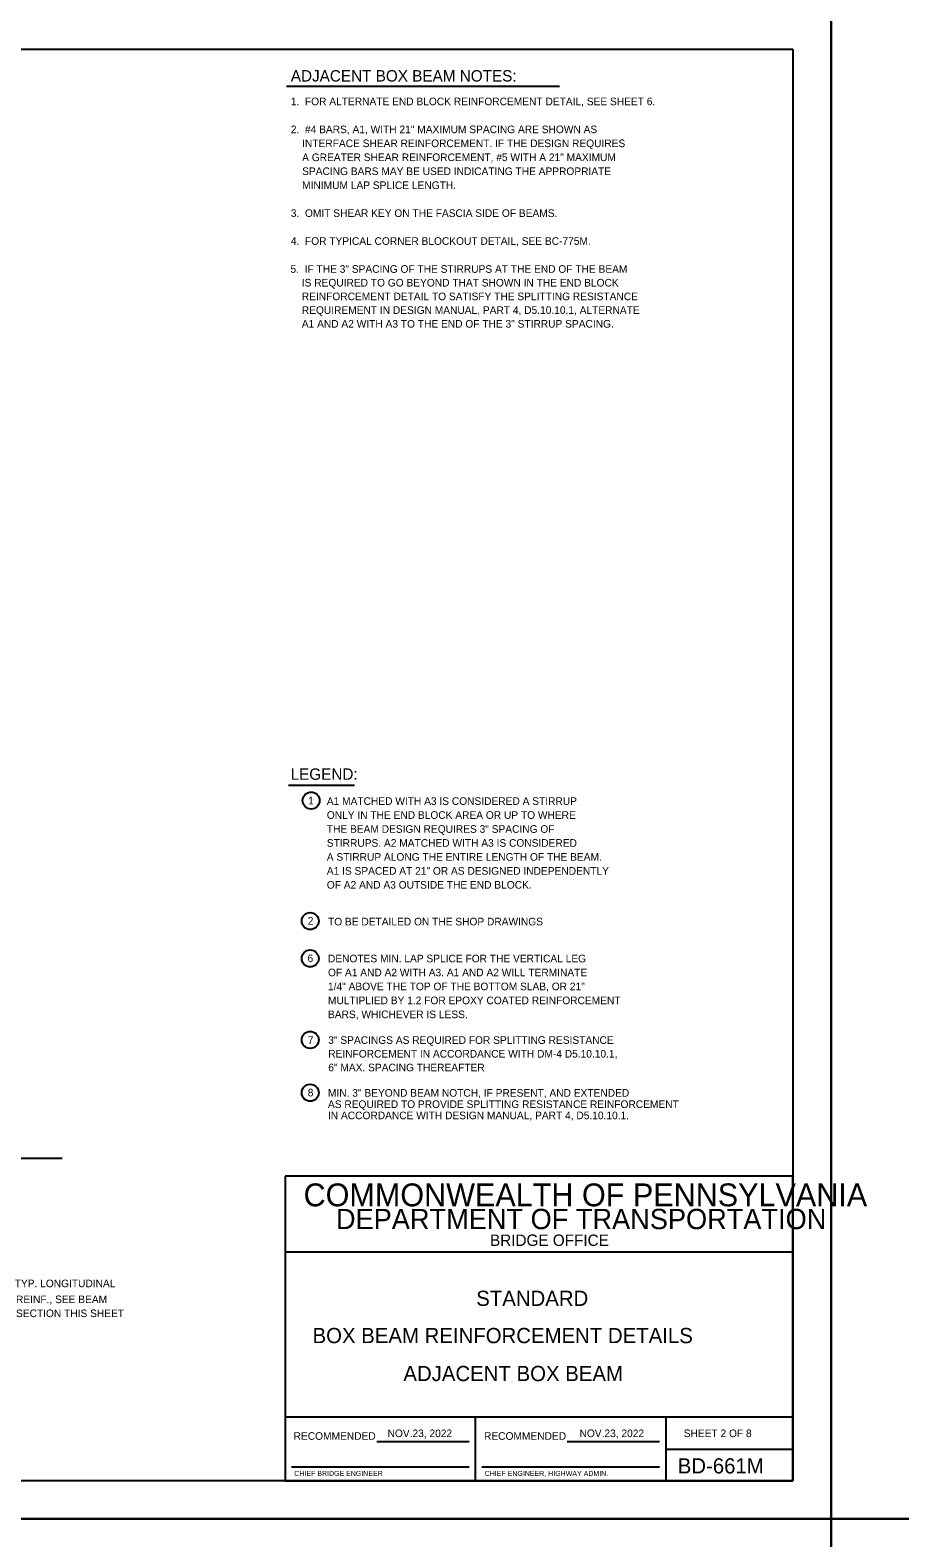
# Model space of a CAD drawing. Extents: x 639331 to 643089, y 299088 to 300975.
# Drawn here: x 641078 to 641420, y 299674 to 300268 of the extents above; entities that cross this region are included whole.
import ezdxf

# ---------------------------------------------------------------- set-up
doc = ezdxf.new("R2010")
doc.units = 0
for name, color, linetype in [('1', 7, 'Continuous'), ('DATES', 7, 'Continuous'), ('PLT-BNDY', 7, 'Continuous'), ('SIGNATORY TITLES', 7, 'Continuous')]:
    doc.layers.add(name, color=color, linetype=linetype)

msp = doc.modelspace()

# ---------------------------------------------------------------- linework, layer by layer
at = {"layer": '1'}
for p, q in [((640592.06, 300260.66), (641378.06, 300260.66)), ((641378.06, 300260.66), (641378.06, 299696.66)), ((641286.13, 300245.94), (641178.53, 300245.94)), ((641179.37, 299970.66), (641205.43, 299970.66)), ((641090.27, 299823.64), (640920.4, 299823.64)), ((641378.06, 299816.66), (641178.06, 299816.66)), ((641178.06, 299816.66), (641178.06, 299696.66)), ((641378.06, 299696.66), (641378.06, 299816.66)), ((641378.06, 299786.66), (641178.06, 299786.66)), ((641378.06, 299721.66), (641178.06, 299721.66)), ((641253.06, 299696.66), (641253.06, 299721.66)), ((641328.06, 299721.66), (641328.06, 299696.66)), ((641214.15, 299712.16), (641250.56, 299712.16)), ((641289.15, 299712.16), (641325.56, 299712.16)), ((641328.06, 299709.16), (641378.06, 299709.16)), ((641180.56, 299702.16), (641250.56, 299702.16)), ((641255.56, 299702.16), (641325.56, 299702.16)), ((641378.06, 299696.66), (640592.06, 299696.66)), ((641178.06, 299696.66), (641378.06, 299696.66))]:
    msp.add_line(p, q, dxfattribs=at)
for centre in [(641188.28, 299964.63), (641187.92, 299917.17), (641187.92, 299902.41), (641187.92, 299870.33), (641187.92, 299849.52)]:
    msp.add_circle(centre, 3.35, dxfattribs=at)
at = {"layer": 'PLT-BNDY'}
for points in [[(640552.06, 300275.66), (641393.06, 300275.66), (641393.06, 299681.66), (640552.06, 299681.66)], [(641393.06, 300275.66), (642234.06, 300275.66), (642234.06, 299681.66), (641393.06, 299681.66)], [(640552.06, 299681.66), (641393.06, 299681.66), (641393.06, 299087.66), (640552.06, 299087.66)], [(641393.06, 299681.66), (642234.06, 299681.66), (642234.06, 299087.66), (641393.06, 299087.66)]]:
    msp.add_lwpolyline(points, close=True, dxfattribs=at)

# ---------------------------------------------------------------- texts
at = {"layer": '1'}
for s, height, p in [('ADJACENT BOX BEAM NOTES:', 4.5, (641180.28, 300247.91)), ('1.  FOR ALTERNATE END BLOCK REINFORCEMENT DETAIL, SEE SHEET 6.', 3, (641180.28, 300238.57)), ('2.  #4 BARS, A1, WITH 21" MAXIMUM SPACING ARE SHOWN AS', 3, (641180.28, 300227.57)), ('    A GREATER SHEAR REINFORCEMENT, #5 WITH A 21" MAXIMUM', 3, (641180.28, 300216.57)), ('    INTERFACE SHEAR REINFORCEMENT. IF THE DESIGN REQUIRES', 3, (641180.28, 300222.07)), ('    SPACING BARS MAY BE USED INDICATING THE APPROPRIATE', 3, (641180.28, 300211.07)), ('    MINIMUM LAP SPLICE LENGTH.', 3, (641180.28, 300205.57)), ('3.  OMIT SHEAR KEY ON THE FASCIA SIDE OF BEAMS.', 3, (641180.28, 300194.57)), ('4.  FOR TYPICAL CORNER BLOCKOUT DETAIL, SEE BC-775M.', 3, (641180.28, 300183.57)), ('5.  IF THE 3" SPACING OF THE STIRRUPS AT THE END OF THE BEAM', 3, (641180.15, 300172.56)), ('    IS REQUIRED TO GO BEYOND THAT SHOWN IN THE END BLOCK', 3, (641180.15, 300167.16)), ('    REINFORCEMENT DETAIL TO SATISFY THE SPLITTING RESISTANCE', 3, (641180.15, 300161.76)), ('    REQUIREMENT IN DESIGN MANUAL, PART 4, D5.10.10.1, ALTERNATE', 3, (641180.15, 300156.36)), ('    A1 AND A2 WITH A3 TO THE END OF THE 3" STIRRUP SPACING.', 3, (641180.15, 300150.96)), ('LEGEND:', 4.5, (641180.19, 299972.8)), ('1', 3, (641187.12, 299963.11)), ('A1 MATCHED WITH A3 IS CONSIDERED A STIRRUP ', 3, (641194.46, 299962.93)), ('ONLY IN THE END BLOCK AREA OR UP TO WHERE', 3, (641194.46, 299957.43)), ('THE BEAM DESIGN REQUIRES 3" SPACING OF', 3, (641194.46, 299951.93)), ('STIRRUPS. A2 MATCHED WITH A3 IS CONSIDERED', 3, (641194.46, 299946.43)), ('A STIRRUP ALONG THE ENTIRE LENGTH OF THE BEAM.', 3, (641194.46, 299940.93)), ('A1 IS SPACED AT 21" OR AS DESIGNED INDEPENDENTLY', 3, (641194.46, 299935.43)), ('OF A2 AND A3 OUTSIDE THE END BLOCK.', 3, (641194.46, 299929.93)), ('2', 3, (641186.95, 299915.73)), ('TO BE DETAILED ON THE SHOP DRAWINGS', 3, (641194.92, 299915.45)), ('6', 3, (641186.87, 299900.97)), ('DENOTES MIN. LAP SPLICE FOR THE VERTICAL LEG ', 3, (641194.92, 299900.9)), ('OF A1 AND A2 WITH A3. A1 AND A2 WILL TERMINATE', 3, (641194.92, 299895.4)), ('1/4" ABOVE THE TOP OF THE BOTTOM SLAB, OR 21"', 3, (641194.92, 299889.9)), ('MULTIPLIED BY 1.2 FOR EPOXY COATED REINFORCEMENT', 3, (641194.92, 299884.4)), ('BARS, WHICHEVER IS LESS.', 3, (641194.92, 299878.9)), ('7', 3, (641186.95, 299868.76)), ('3" SPACINGS AS REQUIRED FOR SPLITTING RESISTANCE', 3, (641195.03, 299868.77)), ('REINFORCEMENT IN ACCORDANCE WITH DM-4 D5.10.10.1,', 3, (641195.03, 299863.37)), ('6" MAX. SPACING THEREAFTER', 3, (641195.03, 299857.97)), ('8', 3, (641186.95, 299848.09)), ('AS REQUIRED TO PROVIDE SPLITTING RESISTANCE REINFORCEMENT', 3, (641194.91, 299843.52)), ('MIN. 3" BEYOND BEAM NOTCH, IF PRESENT, AND EXTENDED', 3, (641194.91, 299847.96)), ('IN ACCORDANCE WITH DESIGN MANUAL, PART 4, D5.10.10.1.', 3, (641194.91, 299839.08)), ('COMMONWEALTH OF PENNSYLVANIA', 9, (641185.31, 299804.78)), ('DEPARTMENT OF TRANSPORTATION', 8.0002, (641198.06, 299795.78)), ('BRIDGE OFFICE', 4.5, (641258.74, 299789.16)), ('TYP. LONGITUDINAL', 3, (641071.52, 299772.89)), ('REINF., SEE BEAM', 3, (641072.03, 299766.62)), ('STANDARD', 6, (641253.31, 299765.53)), ('SECTION THIS SHEET', 3, (641072.03, 299761.12)), ('BOX BEAM REINFORCEMENT DETAILS', 6, (641188.84, 299750.86)), ('ADJACENT BOX BEAM', 6, (641224.62, 299735.9)), ('RECOMMENDED', 3, (641181.39, 299712.78)), ('RECOMMENDED', 3, (641256.39, 299712.78)), ('SHEET 2 OF 8', 3, (641335.05, 299713.84)), ('BD-661M', 6, (641332.68, 299699.53))]:
    msp.add_text(s, height=height, dxfattribs=at).set_placement(p)
at = {"layer": 'DATES'}
for p in [(641218.4, 299713.84), (641294.01, 299713.84)]:
    msp.add_text('NOV.23, 2022', height=3, dxfattribs=at).set_placement(p)
at = {"layer": 'SIGNATORY TITLES'}
for s, p in [('CHIEF BRIDGE ENGINEER', (641181.65, 299698.53)), ('CHIEF ENGINEER, HIGHWAY ADMIN.', (641256.65, 299698.53))]:
    msp.add_text(s, height=2, dxfattribs=at).set_placement(p)

doc.saveas('drawing.dxf')
